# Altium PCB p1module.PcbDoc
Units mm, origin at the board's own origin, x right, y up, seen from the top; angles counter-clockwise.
Board outline 39.81 x 40 mm, 2 copper layers (Top Layer, Bottom Layer); 30 components, 22 nets, 157 pads, 58 vias.
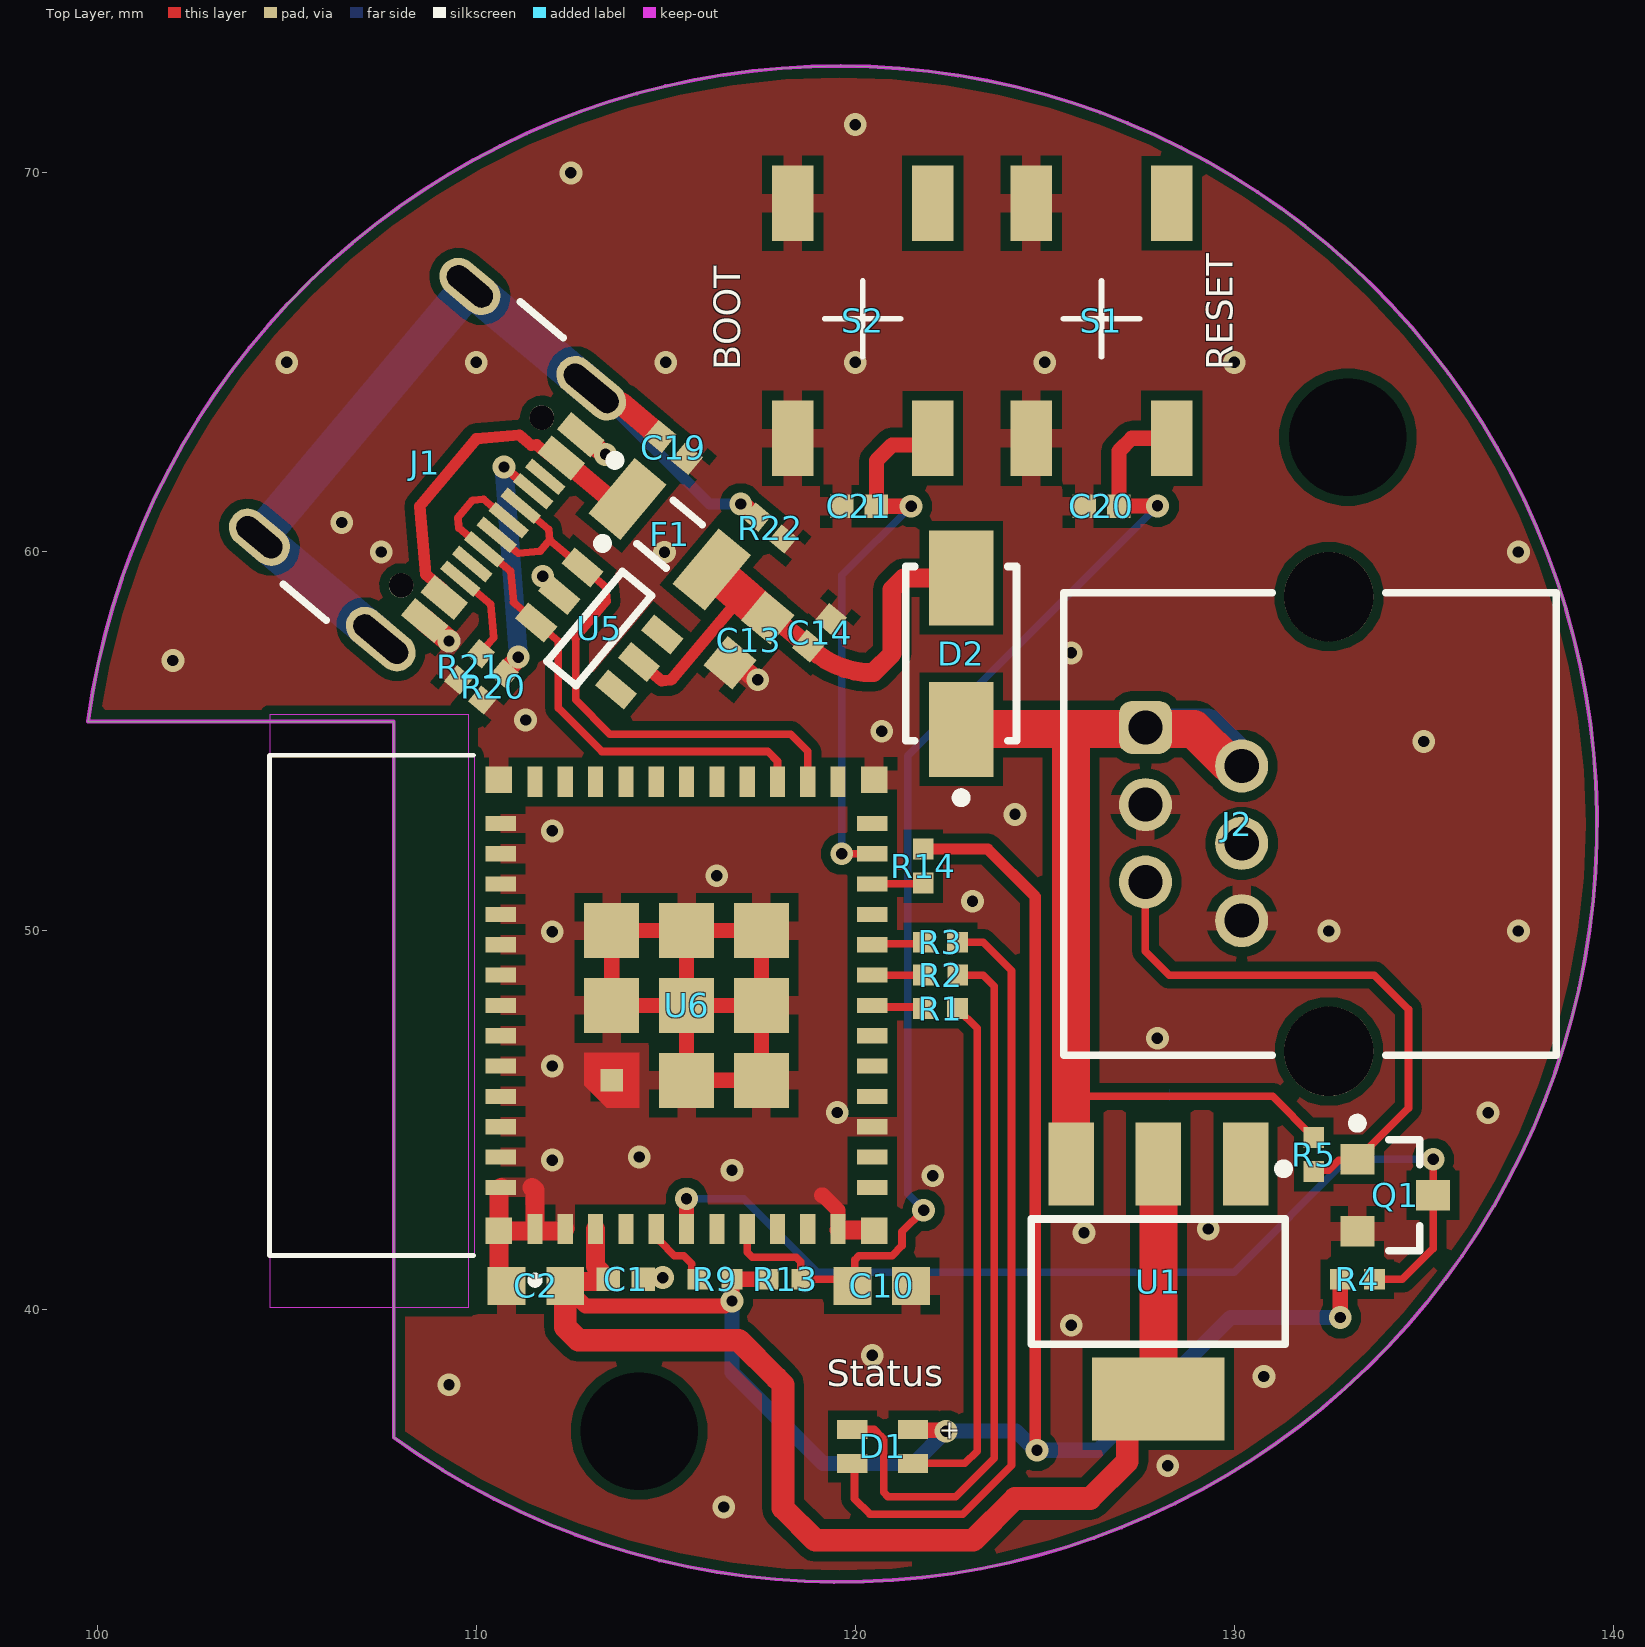
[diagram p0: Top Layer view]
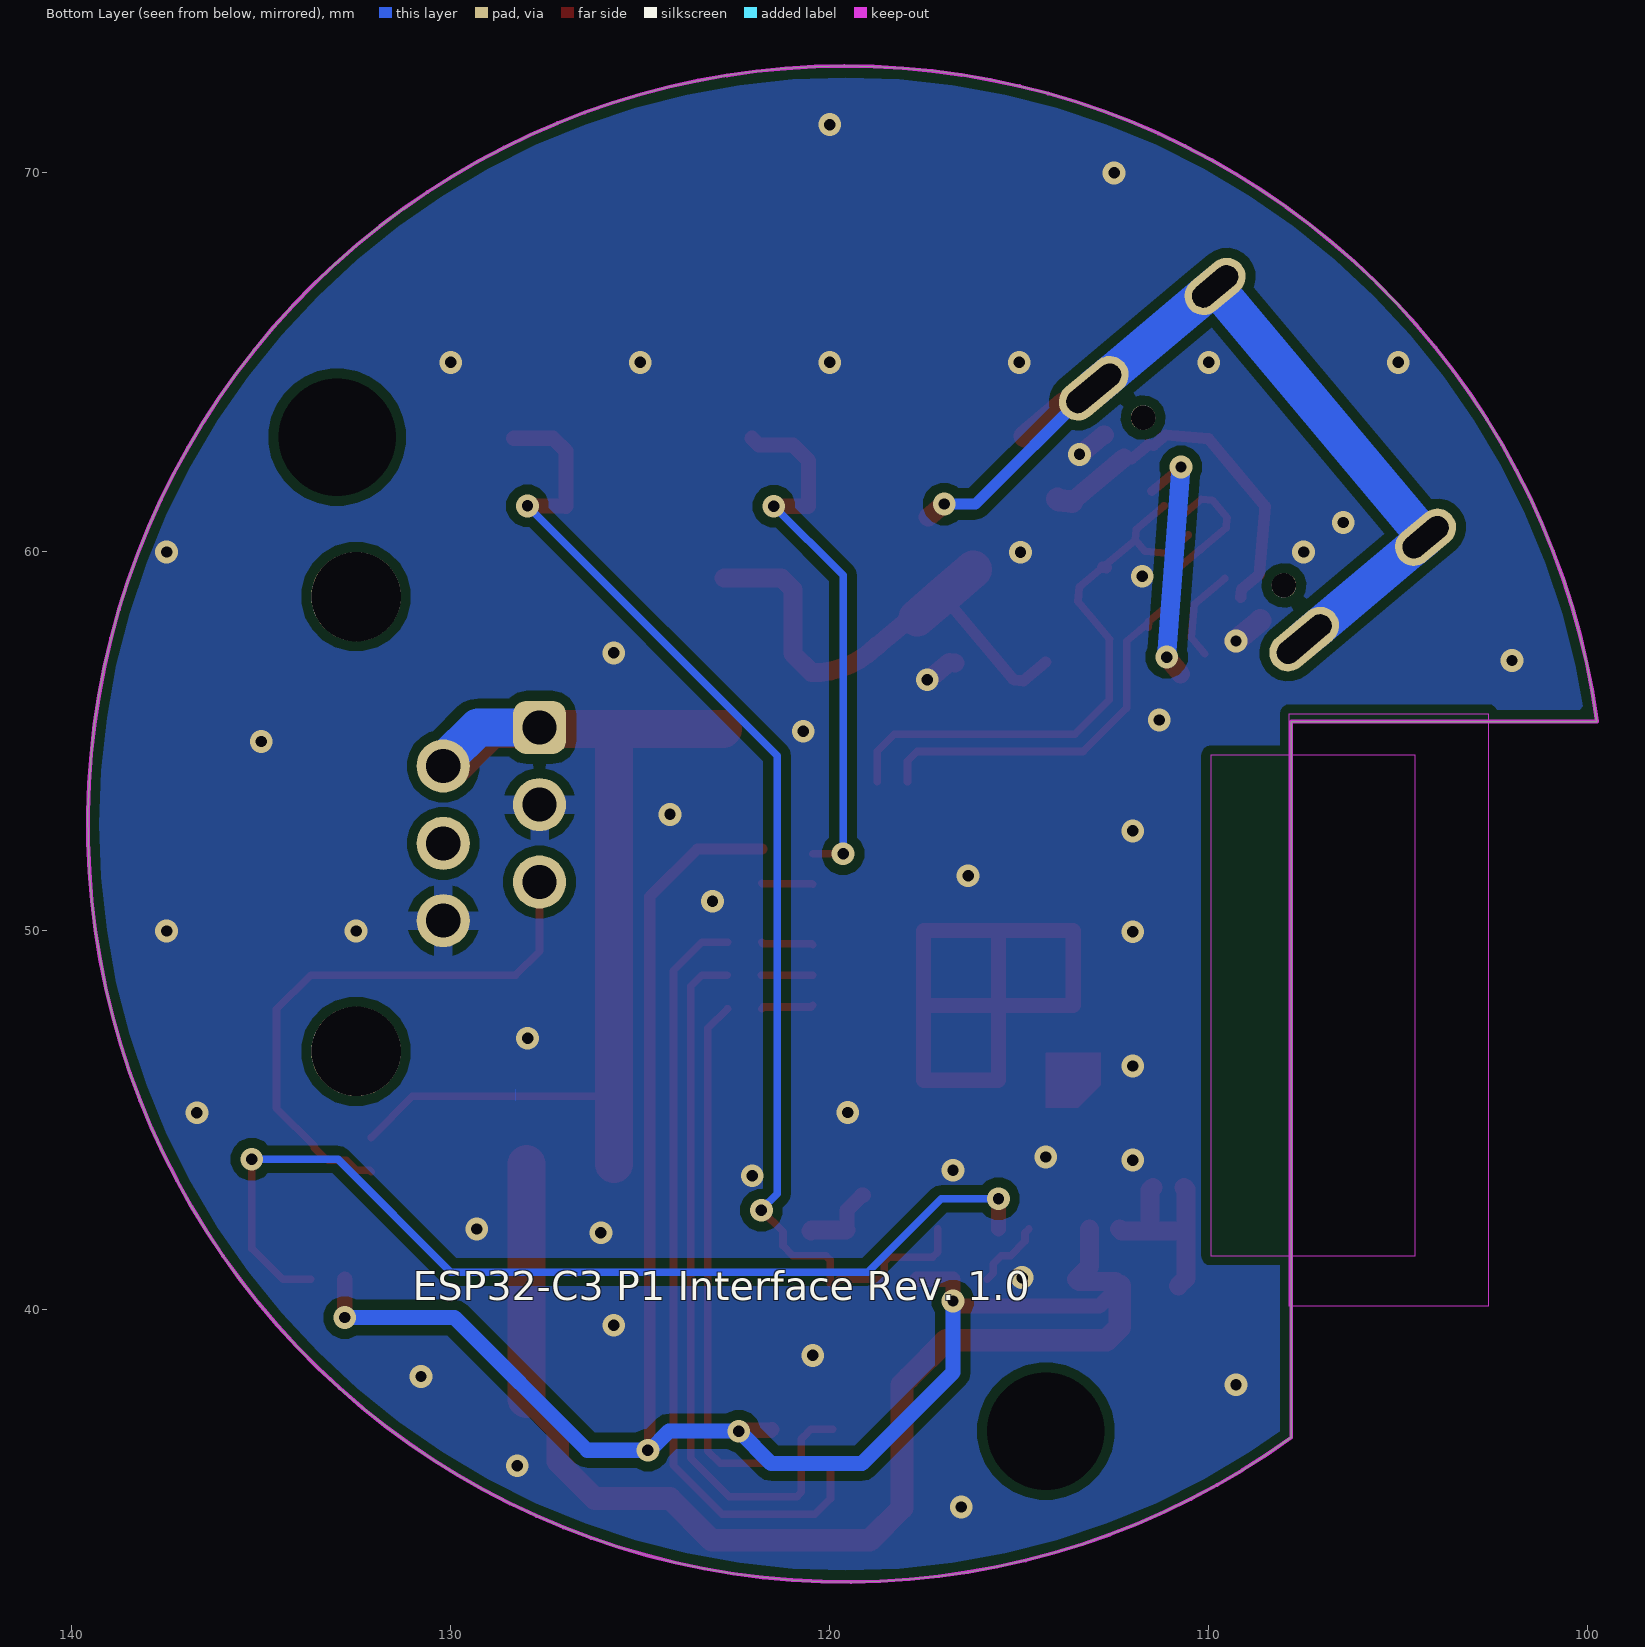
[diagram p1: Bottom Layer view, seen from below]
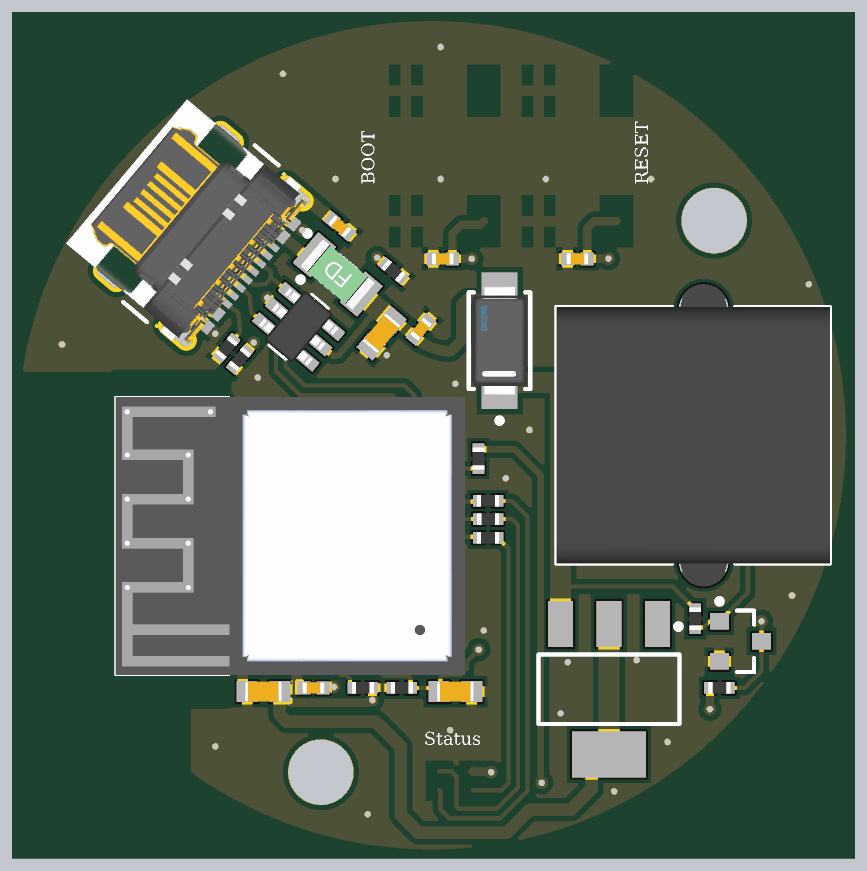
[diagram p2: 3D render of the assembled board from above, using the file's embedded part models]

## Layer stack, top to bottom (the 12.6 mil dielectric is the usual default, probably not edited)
Top Solder: solder mask 0.0102, Solder Resist, Dk 3.5
Top Layer: signal copper 0.0356
Dielectric 1: dielectric 0.32, FR-4, Dk 4.8
Bottom Layer: signal copper 0.0356
Bottom Solder: solder mask 0.0102, Solder Resist, Dk 3.5

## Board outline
107.825,36.637 ccw(c119.576,52.821) 99.76,55.53 99.759,55.525 107.825,55.525

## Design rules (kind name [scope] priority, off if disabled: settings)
Clearance [All] p1: gap=0.254 ignorepadtopadclearanceinfootprint=FALSE except(0: Arc-Hole Track-Hole SMDPad-Hole THPad-Hole Via-Hole Fill-Hole Poly-Hole Region-Hole Text-Hole; 0.2: Arc-SMDPad Arc-THPad Track-SMDPad Track-THPad SMDPad-SMDPad SMDPad-THPad)
PlaneConnect [All] p1: planeconnectstyle=Relief reliefexpansion=0.508 reliefentries=4 reliefconductorwidth=0.5 reliefairgap=0.254
PolygonConnect PolygonConnect_2 [IsVia] p1: connectstyle=Direct reliefconductorwidth=0.254 reliefentries=4 polygonreliefangle="90 Angle" airgapwidth=0.254
PolygonConnect PolygonConnect_1 [(InNet('VBUS') OR InNet('NetF1_2'))] p2: connectstyle=Direct reliefconductorwidth=0.254 reliefentries=4 polygonreliefangle="90 Angle" airgapwidth=0.254
PolygonConnect [All] p3: connectstyle=Relief reliefconductorwidth=0.5 reliefentries=4 polygonreliefangle="90 Angle" airgapwidth=0.254
RoutingVias [All] p1: holewidth=0.711 width=1.27 viastyle="Through Hole" minholewidth=0.711 minwidth=1.27 maxholewidth=0.711 maxwidth=1.27
SolderMaskExpansion [All] p1: expansion=0.102 istentingtop=FALSE
Width [All] p1: maxlimit=1 minlimit=0.2 preferedwidth=0.25 minimp=50.000000 maximp=50.000000 favimp=50.000000
29 further rules are at their usual default settings.

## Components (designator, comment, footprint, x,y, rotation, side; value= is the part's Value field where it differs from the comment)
C1 "0.1uF 0402 10V" CAP_0402 113.952,40.81 r180 top value="100 nF"
C2 "22uF 0603" CAP_0603 111.577,40.635 r0 top value=22uF
C10 "22uF 0603" CAP_0603 120.702,40.635 r180 top value=22uF
C13 "22uF 0603" CAP_0603 117.196,57.669 r50 top value=22uF
C14 "0.1uF 0402 10V" CAP_0402 119.06,57.868 r230 top value="100 nF"
C19 "47pF 0402 50V" CAP_0402 115.206,62.755 r140 top value=47pF
C20 "0.1uF 0402 10V" CAP_0402 126.5,61.207 r0 top value="100 nF"
C21 "0.1uF 0402 10V" CAP_0402 120.102,61.207 r0 top value="100 nF"
D1 "RGB LED" WL-SFCD_0606 1390.725,1306.4 r0 top
D2 "B340A-13-F" FP-SMA-MFG 122.798,57.315 r90 top
F1 "PTC 500mA Hold" "PTC Fuse 1206" 115.106,60.467 r140 top
J1 "USB4105-GF-A" FP-USB4105-GF-A-MFG 107.951,62.947 r230 top
J2 "RJ12 connector" 615006138421 132,52.821 r90 top locked
Q1 "npn" ONSC-SOT-23-3-318-08_V 134.25,43.027 r0 top
R1 "100R 0402" RES_0402 122.25,47.95 r0 top value=100R
R2 "100R 0402" RES_0402 122.256,48.835 r0 top value=100R
R3 "100R 0402" RES_0402 122.25,49.7 r0 top value=100R
R4 "10k 0.5% 0402" RES_0402 133.25,40.81 r180 top value=10k
R5 "4k7 0402" RES_0402 132.1,44.1 r90 top value=4k7
R9 "10k 0.5% 0402" RES_0402 116.302,40.81 r0 top value=10k
R13 "10k 0.5% 0402" RES_0402 118.152,40.81 r180 top value=10k
R14 "10k 0.5% 0402" RES_0402 121.798,51.711 r90 top value=10k
R20 "4k7 0402" RES_0402 110.454,56.44 r50 top value=4k7
R21 "4k7 0402" RES_0402 109.822,56.971 r50 top value=4k7
R22 "1MOhm 0402 5%" RES_0402 117.754,60.628 r140 top value=1Mega
S1 "TACTB-64K-F" TACTB-64K-F 126.5,66.1 r270 top
S2 "TACTB-64K-F" TACTB-64K-F 120.2,66.1 r270 top
U1 "3.3V LDO 1A" SOT230P700X180-4N 128,40.75 r270 top
U5 "SRV05-" SOT95P280X145-6N 113.248,57.98 r320 top
U6 "ESP32-C3-MINI-1-N4" ESP32-C3-MINI-1-N4-Footprint-1 112.852,48.035 r90 top locked

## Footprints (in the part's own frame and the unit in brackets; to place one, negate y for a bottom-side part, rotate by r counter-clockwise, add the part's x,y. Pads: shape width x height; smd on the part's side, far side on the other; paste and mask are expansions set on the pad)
615006138421 [mm] "Modular Jack Horizontal Plastic 6P6C Tab Up"
  rrect50% 1.4x1.4 hole 0.9: 1(2.55,4.34)
  round 1.4 hole 0.9: 2(1.53,1.8) 3(0.51,4.34) 4(-0.51,1.8) 4(-0.51,1.8) 5(-1.53,4.34) 6(-2.55,1.8)
  round 2.36 hole 2.36 unplated: M1(-6,-0.5) M2(6,-0.5)
  silkscreen extent -6.1,-6.5 6.1,6.5, body extent -7.2,-6.5 7.2,6.5, height 14.55
CAP_0402 [mm] "Chip Capacitor, 2-Leads, 0402, IPC Medium Density"
  rect 0.62x0.62 smd: 1(-0.46,0) 2(0.46,0)
  body extent -0.53,-0.28 0.53,0.28, height 0.4
CAP_0603 [mm] "Chip Capacitor, 2-Leads, 0603, IPC Medium Density"
  rect 1x1 smd: 1(-0.775,0) 2(0.775,0)
  body extent -0.87,-0.48 0.87,0.48, height 0.55
ESP32-C3-MINI-1-N4-Footprint-1 [mm]
  rect 0.8x0.4 smd: 1(-5.9,1.3) 2(-5.9,0.5) 3(-5.9,-0.3) 4(-5.9,-1.1) 5(-5.9,-1.9) 6(-5.9,-2.7) 7(-5.9,-3.5) 8(-5.9,-4.3) 9(-5.9,-5.1) 10(-5.9,-5.9) 11(-5.9,-6.7) 25(5.9,-6.7) 26(5.9,-5.9) 27(5.9,-5.1) 28(5.9,-4.3) 29(5.9,-3.5) 30(5.9,-2.7) 31(5.9,-1.9) 32(5.9,-1.1) 33(5.9,-0.3) 34(5.9,0.5) 35(5.9,1.3)
  rect 0.4x0.8 smd: 12(-4.8,-7.6) 13(-4,-7.6) 14(-3.2,-7.6) 15(-2.4,-7.6) 16(-1.6,-7.6) 17(-0.8,-7.6) 18(0,-7.6) 19(0.8,-7.6) 20(1.6,-7.6) 21(2.4,-7.6) 22(3.2,-7.6) 23(4,-7.6) 24(4.8,-7.6) 36(4.8,2.2) 37(4,2.2) 38(3.2,2.2) 39(2.4,2.2) 40(1.6,2.2) 41(0.8,2.2) 42(0,2.2) 43(-0.8,2.2) 44(-1.6,2.2) 45(-2.4,2.2) 46(-3.2,2.2) 47(-4,2.2) 48(-4.8,2.2)
  rect 0.6x0.6 smd paste-1 mask+0: 49_1(-1.975,-0.725)
  rect 1.45x1.45 smd: 49_2(0,-0.725) 49_3(1.975,-0.725) 49_4(1.975,-2.7) 49_5(1.975,-4.675) 49_6(0,-4.675) 49_7(-1.975,-4.675) 49_8(-1.975,-2.7) 49_9(0,-2.7)
  rect 0.7x0.7 smd: 50(5.95,2.25) 51(5.95,-7.65) 52(-5.95,-7.65) 53(-5.95,2.25)
  Top Layer region: -1.25,-1.45 -2.7,-1.45 -2.7,-0.6 -2.1,0 -1.25,0
  Keep-Out Layer region: 6.6,2.9 -6.6,2.9 -6.6,8.3 6.6,8.3
  Keep-Out Layer region: 6.6,2.9 -6.6,2.9 -6.6,8.3 6.6,8.3
  silkscreen extent -7.35,1.2 6.6,8.3, body extent -6.6,-8.3 6.6,8.3, height 2.55
FP-SMA-MFG [mm]
  rect 2.5x1.7 smd paste+0 mask+0: 1(-2,0) 2(2,0)
  silkscreen extent -3.92,-1.46 2.3,1.46, body extent -3.35,-1.56 3.35,1.56, height 0.25
FP-USB4105-GF-A-MFG [mm]
  rrect100% 1x2.1 hole 1.7 slot 0.6 at 0 deg paste-1000 mask+0: 1(-4.32,3.015) 2(4.32,3.015)
  rrect100% 1x1.8 hole 1.4 slot 0.6 at 0 deg paste-1000 mask+0: 3(-4.32,-1.165) 4(4.32,-1.165)
  round 0.65 hole 0.65 unplated paste-1000 mask+0: -(2.89,2.515) --(-2.89,2.515)
  rect 0.6x1.15 smd paste+0 mask+0: A1-B12(-3.2,3.59) A4-B9(-2.4,3.59) B1-A12(3.2,3.59) B4-A9(2.4,3.59)
  rect 0.3x1.15 smd paste+0 mask+0: A5(-1.25,3.59) A6(-0.25,3.59) A7(0.25,3.59) A8(1.25,3.59) B5(1.75,3.59) B6(0.75,3.59) B7(-0.75,3.59) B8(-1.75,3.59)
  silkscreen extent -4.86,0.11 4.87,4.84, body extent -4.97,-3.94 4.97,4.27, height 0.25
ONSC-SOT-23-3-318-08_V [mm] "SOT23, 3-Leads, Body 2.92x1.3mm, Pitch 0.95mm"
  rect 0.9x0.8 smd: 1(-1,0.95) 2(-1,-0.95) 3(1,0)
  silkscreen extent -1.12,-1.46 0.65,2.02, body extent -0.65,-1.46 0.65,1.46, height 1.11
"PTC Fuse 1206" [mm]
  rect 1.1x1.9 smd: 1(-1.45,0) 2(1.45,0)
  silkscreen extent -0.5,-0.74 0.5,0.74, body extent -1.62,-0.82 1.63,0.83, height 0.4
RES_0402 [mm] "Chip Resistor, 2-Leads, 0402, IPC Medium Density"
  rect 0.55x0.55 smd: 1(-0.45,0) 2(0.45,0)
  body extent -0.53,-0.28 0.53,0.28, height 0.4
SOT95P280X145-6N [mm] "SOT23, 6-Leads, Body 2.93x2.80mm, Pitch 0.95mm, IPC Medium Density"
  rect 1x0.55 smd: 1(-1.375,0.95) 2(-1.375,0) 3(-1.375,-0.95) 4(1.375,-0.95) 5(1.375,0) 6(1.375,0.95)
  silkscreen extent -1.5,-1.55 0.5,1.9, body extent -1.5,-1.53 1.5,1.53, height 1.45
SOT230P700X180-4N [mm] "SOT223, 4-Leads, Body 6,50x7,00mm (avg), Pitch 2,30mm, IPC Medium Density"
  rect 2.2x1.2 smd: 1(-3.1,2.3) 2(-3.1,0) 3(-3.1,-2.3)
  rect 2.2x3.5 smd: 2(3.1,0)
  silkscreen extent -3.1,-3.35 1.65,3.43, body extent -1.85,-3.35 1.85,3.35, height 1.8
TACTB-64K-F [mm] "Tactile switch"
  rect 2x1.1 smd: 1(-3.1,1.85) 2(3.1,1.85) 3(-3.1,-1.85) 4(3.1,-1.85)
  silkscreen extent -1.05,-1 0.95,1, body extent -3.32,-2.67 3.23,2.68, height 1.6
WL-SFCD_0606 [mm] "SMD Full-color Chip LED Diffused, body 1.6x1.6mm"
  rect 0.8x0.5 smd: 1(-1270.8,-1270.45) 2(-1270.8,-1269.55) 3(-1269.2,-1269.55) 4(-1269.2,-1270.45)
  body extent -1270.8,-1270.8 -1269.2,-1269.2, height 0.4

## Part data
C1 C14 C20 C21: library part CMP-00101-1, "0.1uF 0402 10V X7R 10%", Tolerance="10 %", Voltage="10 V"
C2 C10 C13: library part CMP-00148-1, "Cap Ceramic 22uF 6.3V X5R 20% SMD 0603 85C Cardboard T/R", Capacitance=22uF, Case Code (Imperial)=0603, Case Code (Metric)=1608, Dielectric=X5R, Max Operating Temperature=85°C, Min Operating Temperature=-55°C, Package Quantity=1, Tolerance=20%, Voltage=6.3V
C19: library part CMP-00099-1, "47pF 0402 50V X7R 5%", Tolerance=10%, Voltage=50V
D1: library part CMP-008-0004-0.0, "WL-SFCD SMT full-color Chip LED Diffused", Case/Package=0606, Forward Current=20mA, Forward Voltage=3.3V, Max Operating Temperature=85°C, Min Operating Temperature=-40°C, Package Quantity=2000
D2: library part CMP-016-0019-1, "Rectifier Diode, Schottky, 1 Phase, 1 Element, 3A, 40V V(RRM), Silicon", Average Rectified Current=3A, Capacitance=250pF, Case/Package=SMA, Forward Voltage=500mV, Max Forward Surge Current (Ifsm)=80A, Max Operating Temperature=125°C, Max Repetitive Reverse Voltage (Vrrm)=40V, Max Reverse Current=500uA, Min Operating Temperature=-55°C, Package Quantity=5000
F1: library part CMP-017-0001-1, "PTC RESET FUSE 8V 500MA 1206", Case/Package=1206, Mfg. Part Number=0ZCJ0050FF2G
J1: library part CMP-003-0034-0.0, "Conn USB 2.0 Type C RCP 24 POS 0.3mm/0.5mm Solder RA SMD 24 Terminal 1 Port T/R", Flammability Rating="UL94 V-0", Insulation Color=Black, Max Operating Temperature=85°C, Min Operating Temperature=-40°C
J2: library part CMP-003-0042-0.0, "Telecom and Datacom Connector, 6 Contact(s), Male, Right Angle, Solder Terminal, Locking, Receptacle", Color=Black, Current Rating=1.5A, Flammability Rating="UL94 V-0", Insulation Resistance=500MR, Max Operating Temperature=85°C, Min Operating Temperature=-40°C, Voltage Rating (AC)=120V
Q1: library part CMP-014-0017-1, "NPN 40V 0.2A SOT23", Case/Package=SOT-23-3, Collector Base Voltage (VCBO)=80V, Collector Emitter Breakdown Voltage=65V, Collector Emitter Saturation Voltage=600mV, Current Rating=100mA, Emitter Base Voltage (VEBO)=6V, Frequency=100MHz, Max Operating Temperature=150°C, Max Power Dissipation=300mW, Min Operating Temperature=-55°C, Package Quantity=1
R1 R2 R3: library part CMP-001-0001-5, "100R 1% 0402 63mW", Case/Package=0402, Power=63mW, Tolerance=1%
R4 R9 R13 R14: library part CMP-0001-00029-2, "RES 10K OHM 0.5% 1/16W 0402", Case/Package=0402, Manufacturer Part No.=RC0402DR-0710KL, Tolerance=0.5%
R5 R20 R21: library part CMP-001-0029-3, "RES SMD 4.7K OHM 1% 1/16W 0402", Case/Package=0402, Mfg. Part Number=RC1005F472CS, Power=1/16W, Tolerance=1
R22: library part CMP-001-0065-1, "RES SMD 1M OHM 5% 1/16W 0402", Case/Package=0402, Mfg. Part Number=CR0402JC1MS001, Power="1/16 W", Tolerance=5%
S1 S2: library part CMP-013-0002-1, "Microswitch TACT; SPST-NO; Positions:2; 0.05A/12VDC;", Case/Package=-
U1: library part CMP-00114-2, "IC REG LINEAR 3.3V 1A SOT223", Case/Package=TO-261-4, Dropout Voltage=1.1V, Max Input Voltage=13V, Max Operating Temperature=125°C, Max Output Current=1A, Min Operating Temperature=-40°C, Operating Supply Current=3.5mA, Output Voltage=3.3V, Package Quantity=4000, Power Supply Rejection Ratio (PSRR)=70dB, Reference Voltage=1.262V
U5: library part CMP-016-0020-1, "SRV05 Series 4 Ch 3.5 pF 15 Vclamp Steering Diode/TVS Array Combo - SOT-23-6", Capacitance=3.5pF, Case/Package=SOT-23, Clamping Voltage=15V, Leakage Current=5uA, Max Operating Temperature=150°C, Min Operating Temperature=-55°C, Peak Pulse Current=5A, Peak Pulse Power=500W, Reverse Breakdown Voltage=6V, Reverse Standoff Voltage=5V, Test Current=1mA
U6: library part CMP-00162-1, "Bluetooth, WiFi 802.11b/g/n, Bluetooth v5.0 Transceiver Module 2.412GHz ~ 2.484GHz PCB Trace Surface Mount"

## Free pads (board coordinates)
  round 0 hole 3.1: 2(114.302,36.802) 2(133,63.027)

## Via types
v1: diameter 0.6, hole 0.3, Top Layer to Bottom Layer, tented both sides, 58 vias

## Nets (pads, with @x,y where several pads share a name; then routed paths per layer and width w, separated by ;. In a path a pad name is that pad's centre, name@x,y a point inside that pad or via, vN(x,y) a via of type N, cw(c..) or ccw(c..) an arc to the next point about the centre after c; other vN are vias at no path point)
3V3: C1.2 C2.2 D1.3 R4.2 R9.2 R13.2 R14.2 U1.2 U6.3 | length 79
  Top Layer w0.3: R14.2 123.495,52.161 124.75,50.906 124.75,36.35 v1(124.8,36.3)
  Top Layer w0.4: C2.2 112.887,40.1 116.562,40.1 116.697,40.235 v1(116.752,40.235) R9.2 R13.2 ; D1.3 121.549,36.826 122.376,36.826 v1(122.4,36.802) ; v1(132.8,39.8) R4.2
  Top Layer w0.5: C2.2 112.467,40.75 113.432,40.75 C1.2 113.152,41.15 U6.3
  Top Layer w0.6: C2.2 112.352,39.551 112.703,39.2 116.927,39.2 117.923,38.204 118.099,38.028 118.099,34.775 118.95,33.923 123.119,33.923 124.218,35.023 126.2,35.023 127.179,36.001 127.179,36.85 127.979,37.65 U1.2@128,37.65
  Top Layer w1: U1.2@128,37.65 U1.2@128,43.85
  Bottom Layer w0.4: v1(116.752,40.235) 116.752,38.348 119.15,35.95 121.548,35.95 v1(122.4,36.802) 124.243,36.802 124.746,36.3 126.4,36.3 129.9,39.8 v1(132.8,39.8)
+5: D2.1 J2.1 J2.2 R5.2 U1.3 | length 30.4
  Top Layer w0.2: U1.3 125.798,43.948 125.798,45.133 ; 125.7,45.537 125.798,45.635 131.015,45.635 R5.2
  Top Layer w1: D2.1@122.812,55.329 125.7,55.329 ; U1.3 125.7,45.133 125.7,45.635 125.7,55.329 ; J2.2 130.123,54.428 129.836,54.428 128.934,55.329 127.66,55.329 125.7,55.329
  Bottom Layer w1: J2.1 129.288,55.371 130.123,54.536 J2.2@130.2,54.536
D+: J1.A6 J1.B6 U5.3 U6.27 | length 15
  Top Layer w0.2: J1.A6 110.195,61.39 109.906,61.365 109.522,60.907 109.546,60.629 J1.B6 110.223,60.065 110.916,59.484 110.987,58.67 111.58,58.172 U5.3 ; U5.3@111.594,58.013 U5.3 ; U6.27 117.952,54.478 117.695,54.735 113.319,54.735 112.171,55.883 112.171,57.643 U5.3
D-: J1.A7 J1.B7 U5.1 U6.26 | length 15.8
  Top Layer w0.2: J1.A7 111.117,59.964 111.685,60.013 111.94,60.317 ; J1.B7 111.915,60.599 111.94,60.317 ; U5.1@112.806,59.581 U5.1 ; U6.26 118.752,54.735 118.298,55.189 113.532,55.189 112.625,56.096 112.625,57.698 112.622,57.701 113.453,58.692 113.419,59.076 U5.1 ; 111.94,60.317 U5.1
  Top Layer w0.3: U5.1@112.709,59.583 U5.1
ENA: C10.2 C20.2 R13.1 S1.2 U6.8 | length 32.8
  Top Layer w0.2: U6.8 117.152,41.525 117.292,41.385 118.451,41.385 118.568,41.268 118.568,40.844 R13.1 119.752,40.81 C10.2 119.984,40.693 119.984,41.318 120.102,41.435 120.976,41.435 121.236,41.695 121.236,42.061 v1(121.806,42.631)
  Top Layer w0.4: v1(127.979,61.214) 127.975,61.21 126.963,61.21 C20.2 126.96,62.66 127.3,63 S1.2
  Bottom Layer w0.2: v1(121.806,42.631) 121.806,42.652 121.392,43.066 121.392,54.627 v1(127.979,61.214)
GND: C1.1 C2.1 C10.1 C13.1 C14.1 C19.1 C20.1 C21.1 J1.A1-B12 J1.B1-A12 J2.3 J2.6 Q1.2 R20.1 R21.1 R22.1 S1.3 S1.4 S2.3 S2.4 U5.2 U6.1 U6.2 U6.11 U6.14 U6.36 U6.37 U6.38 U6.39 U6.40 U6.41 U6.42 U6.43 U6.44 U6.45 U6.46 U6.47 U6.48 U6.49_1 U6.49_2 U6.49_3 U6.49_4 U6.49_5 U6.49_6 U6.49_7 U6.49_8 U6.49_9 U6.50 U6.51 U6.52 U6.53 | length 30
  Top Layer w0.4: 119.113,43.027 119.156,43.027 119.552,42.631 U6.11 ; U6.49_9 U6.49_4 ; U6.49_9 U6.49_8 U6.49_7 U6.49_6 ; U6.49_9 U6.49_6 ; U6.49_9 U6.49_2 U6.49_3 U6.49_4 ; U6.49_4 U6.49_5 U6.49_6
  Top Layer w0.5: U6.48 110.602,43.185 U6.53 ; C2.1 110.602,40.835 U6.53 ; 111.477,43.235 111.552,43.16 U6.1 ; U6.2 112.302,42.085 U6.53 ; J1.A1-B12 112.775,63.092 113.396,62.571 v1(113.414,62.573) ; C13.1 116.847,57.088 117.403,56.622 v1(117.43,56.624) ; U6.11@119.577,42.11 120.477,42.11 U6.52
  Top Layer w0.6: J1.B1-A12 v1(109.284,57.651)
  other v1: 116.531,34.801 128.245,35.892 109.284,38.028 130.786,38.244 120.452,38.801 125.7,39.599 114.927,40.854 126.04,42.035 129.315,42.135 122.046,43.539 116.752,43.689 112.008,43.955 114.302,44.035 119.527,45.21 136.7,45.204 112.008,46.435 127.975,47.166 112.008,49.981 132.5,50 137.5,50 123.095,50.781 116.352,51.458 112.008,52.639 124.218,53.075 135,55 120.7,55.267 111.306,55.564 102,57.137 125.7,57.336 111.759,59.357 107.5,60 114.97,59.994 137.5,60 106.455,60.775 105,65 110,65 115,65 120,65 125,65 130,65 112.5,70 120,71.276
IO3: Q1.3 R4.1 U6.6 | length 26.8
  Top Layer w0.2: R4.1 134.438,40.81 135.25,41.622 Q1.3 v1(135.25,43.977)
  Top Layer w0.4: U6.6 v1(115.552,42.935)
  Bottom Layer w0.2: v1(115.552,42.935) 117.065,42.935 119,41 130,41 132.977,43.977 v1(135.25,43.977)
IO4: R1.1 U6.18 | length 1.4
  Top Layer w0.2: U6.18 120.494,47.993 121.757,47.993 R1.1
IO5: R2.1 U6.19 | length 1.4
  Top Layer w0.2: U6.19 R2.1
IO6: R3.1 U6.20 | length 1.4
  Top Layer w0.2: U6.20 120.484,49.668 121.768,49.668 R3.1
IO9: C21.2 S2.2 U6.23 | length 14.6
  Top Layer w0.2: v1(119.65,52.035) U6.23
  Top Layer w0.4: v1(121.477,61.207) C21.2 120.562,62.411 120.976,62.826 121.876,62.826 S2.2
  Bottom Layer w0.2: v1(119.65,52.035) 119.65,59.381 v1(121.477,61.207)
NetC19_2: C19.2 J1.1 J1.2 J1.3 J1.4 R22.2 | length 25.1
  Top Layer w0.5: v1(116.983,61.265) 116.988,61.265 117.403,60.917 R22.2
  Top Layer w0.6: J1.1 113.542,63.895 113.819,63.919 C19.2
  Bottom Layer w0.3: J1.1 113.105,64.318 116.159,61.265 v1(116.983,61.265)
  Bottom Layer w1: J1.2 107.062,58.053 104.588,60.129 J1.4 J1.3 110.142,66.748 112.616,64.672 J1.1
NetD1_1: D1.1 R3.2 | length 20.6
  Top Layer w0.2: D1.1 119.983,35.892 119.983,35.023 120.393,34.613 122.838,34.613 124.126,35.901 124.126,48.953 123.378,49.7 R3.2
NetD1_2: D1.2 R2.2 | length 19.3
  Top Layer w0.2: D1.2 120.502,36.85 120.691,36.66 120.75,36.602 120.75,35.188 120.867,35.071 122.653,35.071 123.672,36.089 123.672,48.542 123.378,48.835 R2.2
NetD1_3: D1.4 R1.2 | length 13.7
  Top Layer w0.2: D1.4 122.891,35.95 123.218,36.277 123.218,47.432 R1.2
NetF1_2: F1.2 J1.A4-B9 J1.B4-A9 | length 9.6
  Top Layer w0.3: J1.B4-A9 109.14,59.012 108.672,59.404 108.514,61.207 110.006,62.985 111.133,63.083 111.455,62.813 111.596,62.826 111.707,62.732 112.032,62.459 J1.A4-B9
  Top Layer w0.5: J1.A4-B9 F1.2@113.611,61.33
  Top Layer w0.6: F1.2@113.611,61.33 113.963,61.361 F1.2
NetJ1_A5: J1.A5 R20.2 | length 6.6
  Top Layer w0.25: v1(110.735,62.242) J1.A5
  Top Layer w0.5: R20.2 v1(111.113,57.226)
  Bottom Layer w0.5: v1(110.735,62.242) v1(111.113,57.226)
NetJ1_B5: J1.B5 R21.2 | length 2.5
  Top Layer w0.2: J1.B5 110.388,58.617 110.465,57.737 R21.2
NetJ2_5: J2.5 Q1.1 R5.1 | length 15.2
  Top Layer w0.2: J2.5 127.66,49.469 128.294,48.835 133.7,48.835 134.6,47.935 134.6,45.327 133.6,44.327 133.6,44.277 133.3,43.977 Q1.1 133.228,43.955 132.765,43.955 132.5,43.689 132.139,43.689 R5.1
NetR9_1: R9.1 U6.5 | length 1.9
  Top Layer w0.2: U6.5 114.852,42.035 114.852,41.811 115.227,41.435 115.477,41.435 115.689,41.222 115.689,40.972 R9.1
NetR14_1: R14.1 U6.22 | length 1.4
  Top Layer w0.2: U6.22 120.464,51.248 121.785,51.248 R14.1
VBUS: C13.2 C14.2 D2.2 F1.1 U5.5 | length 13.5
  Top Layer w0.3: U5.5 114.894,56.599 115.142,56.62 117.013,58.85
  Top Layer w0.5: C13.2 117.957,58.186 118.715,57.55 C14.2 118.807,57.473 118.809,57.471 ccw(c120.469,59.22) 120.248,56.819 120.272,56.819 120.48,56.819 120.976,57.315 120.976,59.012 121.279,59.315 D2.2
  Top Layer w1: F1.1 117.013,58.85 C13.2
pads on no net: J1.- J1.-- J1.A8 J1.B8 J2.4 J2.M1 J2.M2 S1.1 S2.1 U1.1 U5.4 U5.6 U6.4 U6.7 U6.9 U6.10 U6.12 U6.13 U6.15 U6.16 U6.17 U6.21 U6.24 U6.25 U6.28 U6.29 U6.30 U6.31 U6.32 U6.33 U6.34 U6.35

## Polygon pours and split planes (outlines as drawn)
GND on Bottom Layer "GND_L02_P001" (solid, remove dead copper, pour order 1): 146.175,29.025 145.75,29.45 81.75,29.45 81.75,71.025 93,82.275 148.225,82.275
GND on Top Layer "GND_L01_P000" (solid, remove dead copper, pour order 0): 146.175,29.025 145.75,29.45 81.75,29.45 81.75,71.025 93,82.275 148.225,82.275

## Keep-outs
Top Layer:
  rectangle: 104.55,40.075 109.8,55.7
Bottom Layer:
  rectangle: 102.625,40.1 107.875,55.725
Keep-Out Layer:
  lines w0.1: 99.76,55.53 cw(c119.576,52.821) 107.825,36.637 107.825,40.1 ; 99.759,55.525 107.825,55.525 ; 99.759,55.525 107.825,55.525 ; 99.759,55.525 107.825,55.525 ; 99.759,55.525 107.825,55.525 ; 107.825,40.1 107.825,55.525 ; 107.825,40.1 107.825,55.525 ; 107.825,40.1 107.825,55.525 ; 107.825,40.1 107.825,55.525

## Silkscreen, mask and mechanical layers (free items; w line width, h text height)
Top Overlay:
  text "BOOT" at 117.2,64.8 h1.2 r90
  text "RESET" at 130.2,64.8 h1.2 r90
  text "Status" at 119.25,37.75 h1.2
Bottom Overlay:
  text "ESP32-C3 P1 Interface Rev. 1.0" at 131,40 h1.3
Outline:
  lines w0.1: 99.76,55.53 cw(c119.576,52.821) 107.825,36.637 107.825,40.1 ; 107.825,40.1 107.825,55.525 ; 107.825,40.1 107.825,55.525 ; 107.825,55.525 99.759,55.525 107.825,55.525
Outline (Mech8):
  lines w0.1: 99.759,55.525 107.825,55.525 107.825,40.1 104.143,40.1
  lines w0.254: 99.76,55.53 cw(c119.576,52.821) 104.143,40.1
Drill Drawing:
  lines w0.1: 127.25,54.625 127.5,54.625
